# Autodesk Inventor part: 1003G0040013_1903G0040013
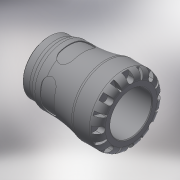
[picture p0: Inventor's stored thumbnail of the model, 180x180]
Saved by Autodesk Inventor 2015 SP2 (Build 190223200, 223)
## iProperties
Created: 2016-12
Part Number: 1003G0040013_1903G0040013
Material: Generic
Description: PLASSON FEMALE ADAPTOR 40x1 1/4" SERIES 1
Document SubType Name: Modeling
Designer: KIM
Mass: 184.652 g
Surface Area: 379.77 cm^2
Volume: 184.652 cm^3
Density: 1 g/cm^3
Appearance: Default
Author: KIM
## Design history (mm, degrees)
derived "1003G.ipt"
feature "Solid1::1003G.ipt"
tag "TaggingFeature1"
body "Solid1"
other parameters: "d1" = 31.08, "d6" = 74, "d8" = 59.5, "d13" = 8, "d14" = 8, "d15" = 0, "d17" = 360 deg, "d19" = 8 deg, "d20" = 0.8, "d21" = 0.8, "d22" = 8 deg, "d24" = 0, "d26" = 360 deg, "d32" = 7, "d33" = 7, "d39" = 1.16856, "d42" = 38.952, "d43" = 54.6, "d46" = 3.33333, "d47" = 19, "d48" = 37.0044, "d50" = 2.31, "d51" = 0.7, "d54" = 14, "d55" = 8.8, "d57" = 15.68, "d58" = 0, "d68" = 360 deg, "d72" = 0.8, "d74" = 0, "d76" = 11.9, "l_" = 74, "G_" = 38.952, "l_2" = 19, "d49" = 7
